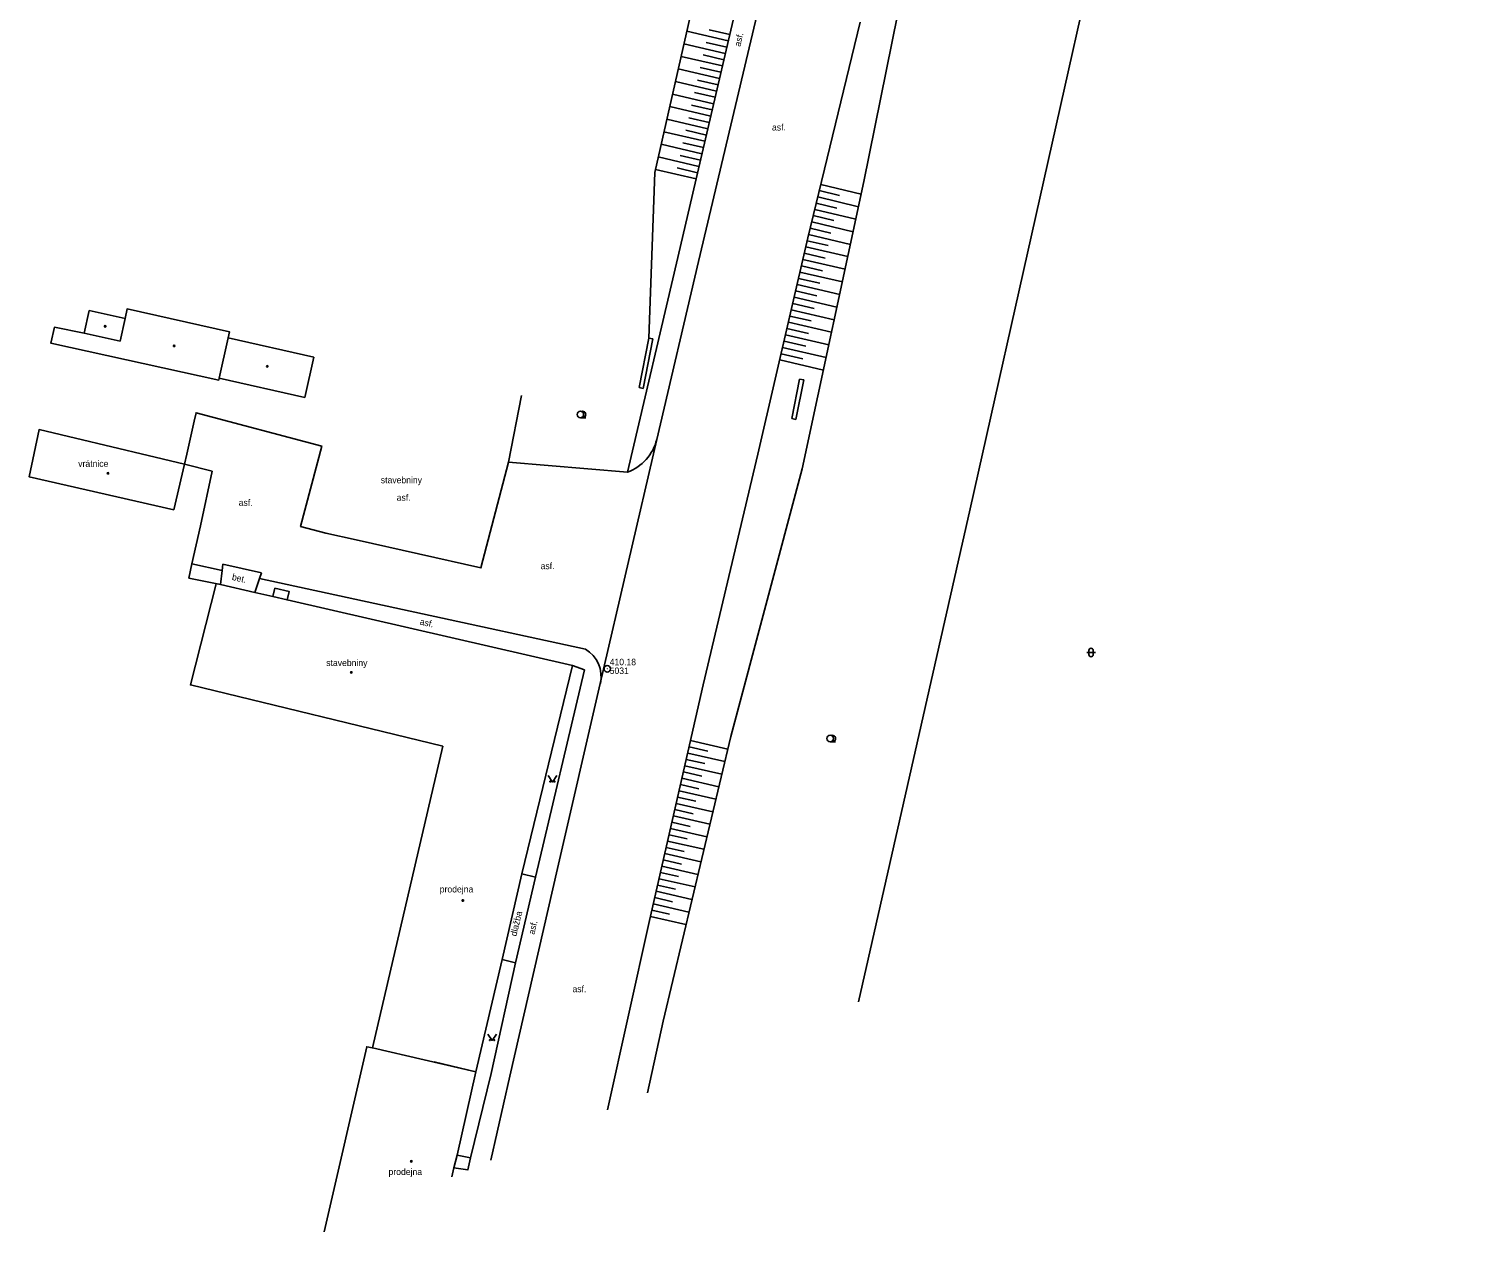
# Model space of a CAD drawing. Extents: x -737488 to -734267, y -1145775 to -1142573.
# Drawn here: x -734897.2 to -734727.9, y -1143238.1 to -1143098.1 of the extents above; entities that cross this region are included whole.
import ezdxf

# ---------------------------------------------------------------- set-up
doc = ezdxf.new("R2010")
doc.units = 0
for name, color, linetype in [('Vrstva 1', 7, 'Continuous'), ('Vrstva 10', 7, 'Continuous'), ('Vrstva 12', 7, 'Continuous'), ('Vrstva 14', 7, 'Continuous'), ('Vrstva 19', 7, 'Continuous'), ('Vrstva 3', 7, 'Continuous'), ('Vrstva 4', 7, 'Continuous'), ('Vrstva 5', 7, 'Continuous'), ('Vrstva 8', 7, 'Continuous'), ('Vrstva 9', 7, 'Continuous')]:
    doc.layers.add(name, color=color, linetype=linetype)

# ---------------------------------------------------------------- blocks, each defined once
blk = doc.blocks.new('1.079')
at = {"layer": 'Vrstva 1'}
for radius in [0.75, 0.001]:
    blk.add_circle((0, -0.001), radius, dxfattribs=at)
blk = doc.blocks.new('3.110')
at = {"layer": 'Vrstva 1'}
blk.add_line((0, -0.75), (1.25, -0.75), dxfattribs=at)
blk.add_circle((0, 0), 0.75, dxfattribs=at)
blk.add_arc((0.5, 0), 0.75, 249.4944, 109.0474, dxfattribs=at)
blk = doc.blocks.new('3.140')
at = {"layer": 'Vrstva 1'}
blk.add_lwpolyline([(-1, 1.5), (0, 0), (1, 1.5)], dxfattribs=at)
for centre in [(-0.5, 0.1), (0.5, 0.1)]:
    blk.add_circle(centre, 0.1, dxfattribs=at)
blk = doc.blocks.new('3.160')
at = {"layer": 'Vrstva 1'}
for p, q in [((-1, 0), (1, 0)), ((-0.5, -0.5), (-0.5, 0.5)), ((0.5, -0.5), (0.5, 0.5))]:
    blk.add_line(p, q, dxfattribs=at)
for centre, start, end in [((0, 0.5), 0, 180), ((0, -0.5), 180, 360)]:
    blk.add_arc(centre, 0.5, start, end, dxfattribs=at)
blk = doc.blocks.new('4.020')
at = {"layer": 'Vrstva 1'}
blk.add_circle((0, 0), 0.175, dxfattribs=at)

msp = doc.modelspace()

# ---------------------------------------------------------------- linework, layer by layer
at = {"layer": 'Vrstva 10'}
for points in [[(-734821.67, -1143124.71), (-734811.45, -1143080.88)], [(-734808.87, -1143081.29), (-734819.27, -1143125.15)], [(-734806.53, -1143122.43), (-734800.43, -1143097.32)], [(-734812.33, -1143147.61), (-734806.53, -1143122.43)], [(-734827.52, -1143149.7), (-734821.67, -1143124.71)], [(-734819.27, -1143125.15), (-734824.11, -1143145.87)], [(-734824.11, -1143145.87), (-734830.68, -1143174.3)], [(-734812.33, -1143147.61), (-734818.7, -1143174.45)], [(-734827.52, -1143149.7), (-734841.37, -1143148.51)], [(-734878.21, -1143160.37), (-734874.71, -1143161.13)], [(-734874.9, -1143162.77), (-734874.71, -1143161.13), (-734874.63, -1143160.41)], [(-734874.63, -1143160.41), (-734870.1, -1143161.39)], [(-734870.1, -1143161.39), (-734870.34, -1143162.07), (-734870.91, -1143163.69)], [(-734870.34, -1143162.07), (-734832.41, -1143170.28)], [(-734832.53, -1143172.7), (-734838.21, -1143196.82)], [(-734833.93, -1143172.2), (-734832.53, -1143172.7)], [(-734830.68, -1143174.3), (-734835.67, -1143195.81)], [(-734818.7, -1143174.45), (-734824.96, -1143201.88)], [(-734835.67, -1143195.81), (-734841.21, -1143219.98)], [(-734840.57, -1143206.79), (-734838.21, -1143196.82)], [(-734838.21, -1143196.82), (-734839.83, -1143196.45)], [(-734824.96, -1143201.88), (-734829.83, -1143223.93)], [(-734840.57, -1143206.79), (-734843.39, -1143219.7)], [(-734842.09, -1143206.43), (-734840.57, -1143206.79)], [(-734843.39, -1143219.7), (-734845.78, -1143229.51)], [(-734841.21, -1143219.98), (-734843.42, -1143229.78)], [(-734847.72, -1143230.66), (-734846.11, -1143230.91)], [(-734847.33, -1143229.21), (-734845.78, -1143229.51)], [(-734846.11, -1143230.91), (-734845.78, -1143229.51)], [(-734846.11, -1143230.91), (-734846.12, -1143230.93)]]:
    msp.add_lwpolyline(points, dxfattribs=at)
for centre, radius, start, end in [((-734829.44, -1143144.56), 5.49, 290.466, 346.1742), ((-734834.33, -1143173.49), 3.74, 347.5088, 59.0603)]:
    msp.add_arc(centre, radius, start, end, dxfattribs=at)
at = {"layer": 'Vrstva 12'}
for points in [[(-734800, -1143115.86), (-734792.16, -1143077.08)], [(-734816.58, -1143080.55), (-734824.34, -1143114.81)], [(-734815.79, -1143099.49), (-734820.62, -1143098.37)], [(-734815.62, -1143098.76), (-734818.03, -1143098.2)], [(-734816.13, -1143100.95), (-734820.95, -1143099.83)], [(-734815.96, -1143100.22), (-734818.37, -1143099.66)], [(-734816.47, -1143102.41), (-734821.28, -1143101.29)], [(-734816.3, -1143101.68), (-734818.71, -1143101.12)], [(-734816.81, -1143103.87), (-734821.61, -1143102.75)], [(-734816.64, -1143103.14), (-734819.04, -1143102.58)], [(-734817.15, -1143105.33), (-734821.94, -1143104.22)], [(-734817.32, -1143106.06), (-734819.71, -1143105.51)], [(-734816.98, -1143104.6), (-734819.38, -1143104.05)], [(-734817.83, -1143108.26), (-734822.6, -1143107.14)], [(-734817.49, -1143106.8), (-734822.27, -1143105.68)], [(-734817.66, -1143107.53), (-734820.05, -1143106.97)], [(-734818.17, -1143109.72), (-734822.94, -1143108.61)], [(-734818, -1143108.99), (-734820.39, -1143108.43)], [(-734818.52, -1143111.18), (-734823.27, -1143110.07)], [(-734818.34, -1143110.45), (-734820.72, -1143109.89)], [(-734818.86, -1143112.64), (-734823.6, -1143111.53)], [(-734818.69, -1143111.91), (-734821.06, -1143111.35)], [(-734819.2, -1143114.1), (-734823.93, -1143113)], [(-734819.03, -1143113.37), (-734821.39, -1143112.82)], [(-734824.34, -1143114.81), (-734825.05, -1143134.09)], [(-734819.54, -1143115.56), (-734824.26, -1143114.46)], [(-734819.37, -1143114.83), (-734821.73, -1143114.28)], [(-734807.18, -1143149.31), (-734800, -1143115.86)], [(-734805.19, -1143116.91), (-734802.83, -1143117.49)], [(-734805.01, -1143116.19), (-734800.32, -1143117.33)], [(-734805.54, -1143118.37), (-734803.17, -1143118.95)], [(-734805.37, -1143117.64), (-734800.63, -1143118.79)], [(-734806.08, -1143120.56), (-734801.26, -1143121.73)], [(-734805.9, -1143119.83), (-734803.5, -1143120.41)], [(-734805.72, -1143119.1), (-734800.95, -1143120.26)], [(-734806.43, -1143122.02), (-734801.58, -1143123.2)], [(-734806.25, -1143121.29), (-734803.84, -1143121.88)], [(-734806.77, -1143123.48), (-734801.88, -1143124.6)], [(-734806.6, -1143122.75), (-734804.16, -1143123.31)], [(-734807.28, -1143125.67), (-734804.81, -1143126.24)], [(-734807.11, -1143124.94), (-734802.19, -1143126.07)], [(-734806.94, -1143124.21), (-734804.49, -1143124.77)], [(-734807.61, -1143127.13), (-734805.14, -1143127.7)], [(-734807.44, -1143126.4), (-734802.51, -1143127.54)], [(-734807.95, -1143128.59), (-734805.46, -1143129.17)], [(-734807.78, -1143127.86), (-734802.82, -1143129)], [(-734808.46, -1143130.79), (-734803.45, -1143131.94)], [(-734808.29, -1143130.05), (-734805.79, -1143130.63)], [(-734808.12, -1143129.32), (-734803.14, -1143130.47)], [(-734808.79, -1143132.25), (-734803.77, -1143133.4)], [(-734808.62, -1143131.52), (-734806.12, -1143132.09)], [(-734809.13, -1143133.71), (-734804.08, -1143134.87)], [(-734808.96, -1143132.98), (-734806.44, -1143133.56)], [(-734809.63, -1143135.9), (-734807.09, -1143136.49)], [(-734809.47, -1143135.17), (-734804.4, -1143136.34)], [(-734809.3, -1143134.44), (-734806.77, -1143135.02)], [(-734809.8, -1143136.63), (-734804.71, -1143137.81)], [(-734815.5, -1143180.46), (-734807.18, -1143149.31)], [(-734823.38, -1143213.6), (-734815.5, -1143180.46)], [(-734820.35, -1143181.66), (-734818.18, -1143182.16)], [(-734820.18, -1143180.93), (-734815.85, -1143181.92)], [(-734820.68, -1143183.12), (-734818.52, -1143183.62)], [(-734820.51, -1143182.39), (-734816.19, -1143183.38)], [(-734821.01, -1143184.59), (-734818.86, -1143185.08)], [(-734820.85, -1143183.86), (-734816.54, -1143184.84)], [(-734821.35, -1143186.05), (-734819.2, -1143186.54)], [(-734821.18, -1143185.32), (-734816.89, -1143186.3)], [(-734821.85, -1143188.24), (-734817.58, -1143189.22)], [(-734821.68, -1143187.51), (-734819.55, -1143188)], [(-734821.51, -1143186.78), (-734817.24, -1143187.76)], [(-734822.18, -1143189.71), (-734817.93, -1143190.68)], [(-734822.01, -1143188.97), (-734819.89, -1143189.46)], [(-734822.52, -1143191.17), (-734818.28, -1143192.14)], [(-734822.35, -1143190.44), (-734820.23, -1143190.92)], [(-734823.02, -1143193.36), (-734820.91, -1143193.84)], [(-734822.85, -1143192.63), (-734818.62, -1143193.59)], [(-734822.68, -1143191.9), (-734820.57, -1143192.38)], [(-734823.35, -1143194.82), (-734821.25, -1143195.3)], [(-734823.18, -1143194.09), (-734818.97, -1143195.05)], [(-734823.68, -1143196.29), (-734821.59, -1143196.76)], [(-734823.52, -1143195.55), (-734819.32, -1143196.51)], [(-734824.18, -1143198.48), (-734820.01, -1143199.43)], [(-734824.02, -1143197.75), (-734821.93, -1143198.23)], [(-734823.85, -1143197.02), (-734819.66, -1143197.97)], [(-734824.52, -1143199.94), (-734820.36, -1143200.89)], [(-734824.35, -1143199.21), (-734822.27, -1143199.69)], [(-734824.85, -1143201.4), (-734820.71, -1143202.35)], [(-734824.68, -1143200.67), (-734822.61, -1143201.15)], [(-734825.2, -1143221.93), (-734823.38, -1143213.6)]]:
    msp.add_lwpolyline(points, dxfattribs=at)
at = {"layer": 'Vrstva 4'}
for points in [[(-734879.08, -1143148.75), (-734880.31, -1143154.07)], [(-734878.58, -1143162.03), (-734874.9, -1143162.77)], [(-734870.91, -1143163.69), (-734868.78, -1143164.18), (-734867.13, -1143164.56), (-734833.93, -1143172.2), (-734839.83, -1143196.45), (-734842.09, -1143206.43), (-734845.16, -1143219.48)], [(-734850.03, -1143218.34), (-734845.16, -1143219.48)], [(-734845.16, -1143219.48), (-734847.33, -1143229.21), (-734847.72, -1143230.66), (-734847.96, -1143231.73)]]:
    msp.add_lwpolyline(points, dxfattribs=at)
at = {"layer": 'Vrstva 5'}
for points in [[(-734890.18, -1143130.88), (-734890.77, -1143133.51)], [(-734885.99, -1143131.82), (-734890.18, -1143130.88)], [(-734873.98, -1143134.04), (-734873.85, -1143133.34), (-734885.77, -1143130.69), (-734885.99, -1143131.82)], [(-734886.58, -1143134.45), (-734885.99, -1143131.82)], [(-734890.77, -1143133.51), (-734894.22, -1143132.82), (-734894.63, -1143134.68), (-734875.1, -1143138.98), (-734875.05, -1143138.76)], [(-734890.77, -1143133.51), (-734886.58, -1143134.45)], [(-734873.98, -1143134.04), (-734875.05, -1143138.76)], [(-734864.02, -1143136.29), (-734873.98, -1143134.04)], [(-734865.09, -1143141.01), (-734864.02, -1143136.29)], [(-734875.05, -1143138.76), (-734865.09, -1143141.01)], [(-734880.31, -1143154.07), (-734897.17, -1143150.22), (-734896.01, -1143144.74), (-734879.08, -1143148.75)], [(-734845.16, -1143219.48), (-734857.2, -1143216.7), (-734849.02, -1143181.59), (-734878.39, -1143174.45), (-734875.39, -1143162.67)], [(-734857.2, -1143216.7), (-734857.87, -1143216.57), (-734862.83, -1143238.13)]]:
    msp.add_lwpolyline(points, dxfattribs=at)
at = {"layer": 'Vrstva 9'}
for points in [[(-734679.48, -1142673.32), (-734742.83, -1142954.66), (-734754.39, -1143005.54), (-734763.3, -1143045.45), (-734787.63, -1143153.95), (-734800.62, -1143211.35)], [(-734826.17, -1143139.84), (-734825.05, -1143134.09)], [(-734825.68, -1143139.94), (-734824.56, -1143134.19)], [(-734825.05, -1143134.09), (-734824.56, -1143134.19)], [(-734808.4, -1143143.46), (-734807.48, -1143138.86)], [(-734807.91, -1143143.56), (-734806.99, -1143138.96)], [(-734807.48, -1143138.86), (-734806.99, -1143138.96)], [(-734859.1, -1143157.58), (-734844.57, -1143160.84), (-734841.37, -1143148.51), (-734839.85, -1143140.76)], [(-734826.17, -1143139.84), (-734825.68, -1143139.94)], [(-734878.81, -1143147.6), (-734877.96, -1143143.76)], [(-734877.96, -1143143.76), (-734877.74, -1143142.78), (-734863.11, -1143146.65), (-734865.56, -1143156.03), (-734862.62, -1143156.79)], [(-734808.4, -1143143.46), (-734807.91, -1143143.56)], [(-734879.08, -1143148.75), (-734878.81, -1143147.6)], [(-734877.21, -1143155.95), (-734875.86, -1143149.59), (-734879.08, -1143148.75)], [(-734877.21, -1143155.95), (-734878.21, -1143160.37)], [(-734859.1, -1143157.58), (-734862.62, -1143156.79)], [(-734878.58, -1143162.03), (-734878.21, -1143160.37)], [(-734874.9, -1143162.77), (-734870.91, -1143163.69)], [(-734868.78, -1143164.18), (-734868.55, -1143163.2), (-734866.9, -1143163.57), (-734867.13, -1143164.56)]]:
    msp.add_lwpolyline(points, dxfattribs=at)

# ---------------------------------------------------------------- block references
at = {"layer": 'Vrstva 1', "xscale": 0.5, "yscale": 0.5}
msp.add_blockref('1.079', (-734829.87, -1143172.58), dxfattribs=at)
at = {"layer": 'Vrstva 3', "xscale": 0.5, "yscale": 0.5}
for name, p in [('3.110', (-734833, -1143142.98)), ('3.160', (-734773.56, -1143170.68)), ('3.110', (-734803.93, -1143180.69)), ('3.140', (-734836.26, -1143185.76)), ('3.140', (-734843.28, -1143215.84))]:
    msp.add_blockref(name, p, dxfattribs=at)
at = {"layer": 'Vrstva 8', "xscale": 0.5, "yscale": 0.5}
for p in [(-734888.31, -1143132.71), (-734880.28, -1143134.99), (-734869.45, -1143137.38), (-734887.99, -1143149.82), (-734859.66, -1143173), (-734846.68, -1143199.55), (-734852.68, -1143229.91)]:
    msp.add_blockref('4.020', p, dxfattribs=at)

# ---------------------------------------------------------------- texts
at = {"layer": 'Vrstva 14'}
for s, rotation, p in [('asf.', 76.66, (-734814.38, -1143100.2)), ('bet.', 347.016, (-734873.61, -1143162.22)), ('asf.', 347.041, (-734851.75, -1143167.42)), ('dlažba', 76.683, (-734840.44, -1143203.76)), ('asf.', 77.09, (-734838.35, -1143203.56))]:
    msp.add_text(s, height=0.75, rotation=rotation, dxfattribs=at).set_placement(p)
for s, p in [('asf.', (-734810.7, -1143109.92)), ('vrátnice', (-734891.45, -1143149.07)), ('stavebniny', (-734856.23, -1143150.98)), ('asf.', (-734872.77, -1143153.61)), ('asf.', (-734854.38, -1143153.02)), ('asf.', (-734837.63, -1143160.98)), ('stavebniny', (-734862.58, -1143172.26)), ('prodejna', (-734849.37, -1143198.61)), ('asf.', (-734833.92, -1143210.22)), ('prodejna', (-734855.33, -1143231.5))]:
    msp.add_text(s, height=0.75, dxfattribs=at).set_placement(p)
at = {"layer": 'Vrstva 19'}
for s, p in [(' 410.18', (-734829.87, -1143172.16)), (' 5031', (-734829.87, -1143173.18))]:
    msp.add_text(s, height=0.75, dxfattribs=at).set_placement(p)

doc.saveas('drawing.dxf')
